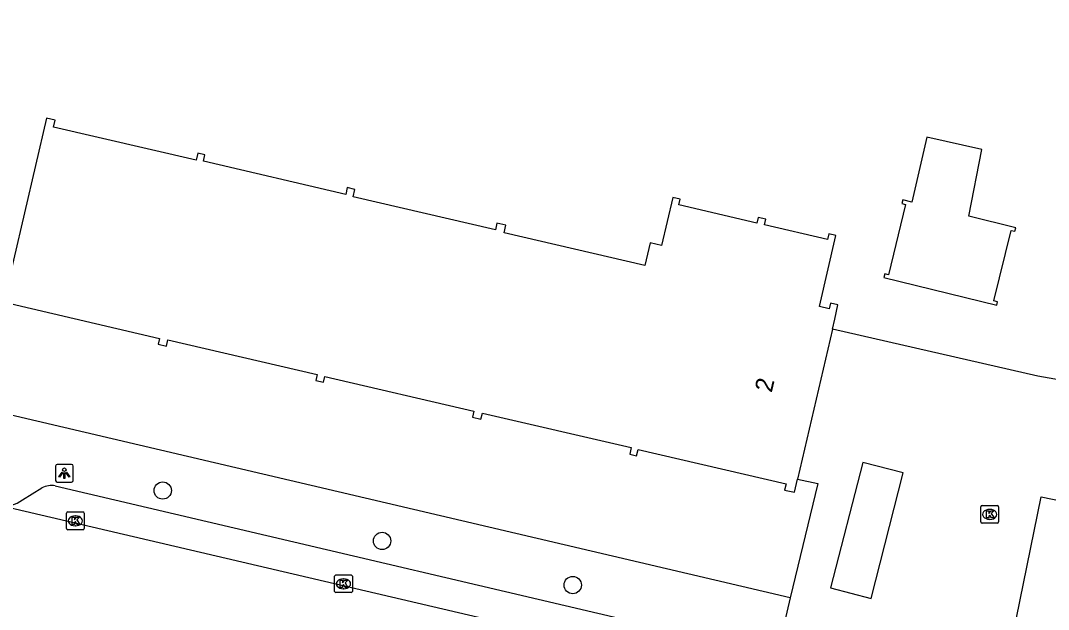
# Model space of a CAD drawing. Extents: x 163686 to 164493, y 382719 to 383870.
# Drawn here: x 163913.6 to 163971.7, y 383334.7 to 383368 of the extents above; entities that cross this region are included whole.
import ezdxf

# ---------------------------------------------------------------- set-up
doc = ezdxf.new("R2010")
doc.units = 0
for name, color, linetype in [('IMGEO_Boom', 7, 'Continuous'), ('IMGEO_Kolk', 7, 'Continuous'), ('IMGEO_Lichtpunt', 7, 'Continuous'), ('IMGEO_Pand', 7, 'Continuous'), ('IMGEO_Pand_nummerreeks', 7, 'Continuous'), ('IMGEO_Rijbaan_lokaal_open', 7, 'Continuous'), ('IMGEO_Voetpad_open', 7, 'Continuous')]:
    doc.layers.add(name, color=color, linetype=linetype)

msp = doc.modelspace()

# ---------------------------------------------------------------- linework, layer by layer
at = {"layer": 'IMGEO_Boom'}
for centre in [(163921.64, 383341.41), (163934.047, 383338.559), (163944.827, 383336.066)]:
    msp.add_circle(centre, 0.489, dxfattribs=at)
at = {"layer": 'IMGEO_Kolk'}
for p, q in [((163916.274, 383340.196), (163917.126, 383340.196)), ((163967.905, 383339.635), (163967.905, 383340.487)), ((163967.98, 383340.561), (163968.832, 383340.561)), ((163968.393, 383340.341), (163968.418, 383340.341)), ((163968.906, 383340.487), (163968.906, 383339.635)), ((163916.199, 383339.27), (163916.199, 383340.122)), ((163916.687, 383339.976), (163916.712, 383339.976)), ((163917.2, 383340.122), (163917.2, 383339.27)), ((163968.416, 383339.781), (163968.391, 383339.781)), ((163917.126, 383339.196), (163916.274, 383339.196)), ((163916.71, 383339.416), (163916.685, 383339.416)), ((163968.832, 383339.561), (163967.98, 383339.561)), ((163931.362, 383335.711), (163931.362, 383336.563)), ((163931.437, 383336.637), (163932.289, 383336.637)), ((163931.85, 383336.417), (163931.875, 383336.417)), ((163932.363, 383336.563), (163932.363, 383335.711)), ((163932.289, 383335.637), (163931.437, 383335.637)), ((163931.873, 383335.857), (163931.848, 383335.857))]:
    msp.add_line(p, q, dxfattribs=at)
for points in [[(163916.274, 383340.196), (163917.126, 383340.196)], [(163967.905, 383339.635), (163967.905, 383340.487)], [(163967.98, 383340.561), (163968.832, 383340.561)], [(163968.226, 383340.261), (163968.349, 383340.261), (163968.349, 383340.11), (163968.479, 383340.261), (163968.643, 383340.261), (163968.497, 383340.11), (163968.65, 383339.861), (163968.498, 383339.861), (163968.413, 383340.025), (163968.349, 383339.958), (163968.349, 383339.861), (163968.226, 383339.861), (163968.226, 383340.261)], [(163968.906, 383340.487), (163968.906, 383339.635)], [(163916.199, 383339.27), (163916.199, 383340.122)], [(163916.52, 383339.896), (163916.643, 383339.896), (163916.643, 383339.745), (163916.773, 383339.896), (163916.937, 383339.896), (163916.791, 383339.745), (163916.944, 383339.496), (163916.792, 383339.496), (163916.707, 383339.66), (163916.643, 383339.593), (163916.643, 383339.496), (163916.52, 383339.496), (163916.52, 383339.896)], [(163917.2, 383340.122), (163917.2, 383339.27)], [(163917.126, 383339.196), (163916.274, 383339.196)], [(163968.832, 383339.561), (163967.98, 383339.561)], [(163931.362, 383335.711), (163931.362, 383336.563)], [(163931.437, 383336.637), (163932.289, 383336.637)], [(163931.683, 383336.337), (163931.806, 383336.337), (163931.806, 383336.186), (163931.936, 383336.337), (163932.1, 383336.337), (163931.954, 383336.186), (163932.107, 383335.937), (163931.955, 383335.937), (163931.87, 383336.101), (163931.806, 383336.034), (163931.806, 383335.937), (163931.683, 383335.937), (163931.683, 383336.337)], [(163932.363, 383336.563), (163932.363, 383335.711)], [(163932.289, 383335.637), (163931.437, 383335.637)]]:
    msp.add_lwpolyline(points, dxfattribs=at)
for centre, start, end in [((163916.276, 383340.12), 91.55205, 178.44795), ((163916.276, 383340.12), 91.55205, 178.44795), ((163917.124, 383340.12), 1.55205, 88.44795), ((163917.124, 383340.12), 1.55205, 88.44795), ((163967.982, 383340.485), 91.55205, 178.44795), ((163967.982, 383340.485), 91.55205, 178.44795), ((163968.83, 383340.485), 1.55205, 88.44795), ((163968.83, 383340.485), 1.55205, 88.44795), ((163967.982, 383339.637), 181.55205, 268.44795), ((163967.982, 383339.637), 181.55205, 268.44795), ((163968.83, 383339.637), 271.55205, 358.44795), ((163968.83, 383339.637), 271.55205, 358.44795), ((163916.276, 383339.272), 181.55205, 268.44795), ((163916.276, 383339.272), 181.55205, 268.44795), ((163917.124, 383339.272), 271.55205, 358.44795), ((163917.124, 383339.272), 271.55205, 358.44795), ((163931.439, 383336.561), 91.55205, 178.44795), ((163931.439, 383336.561), 91.55205, 178.44795), ((163932.287, 383336.561), 1.55205, 88.44795), ((163932.287, 383336.561), 1.55205, 88.44795), ((163931.439, 383335.713), 181.55205, 268.44795), ((163931.439, 383335.713), 181.55205, 268.44795), ((163932.287, 383335.713), 271.55205, 358.44795), ((163932.287, 383335.713), 271.55205, 358.44795)]:
    msp.add_arc(centre, 0.0765, start, end, dxfattribs=at)
for centre, major_axis, ratio, start_param, end_param in [((163968.392, 383340.061), (-0.387, 0.002), 0.722429, 4.712389, 7.853982), ((163968.417, 383340.061), (-0.39, 0.002), 0.717154, 1.570796, 4.712389), ((163916.686, 383339.696), (-0.387, 0.002), 0.722429, 4.712389, 7.853982), ((163916.711, 383339.696), (-0.39, 0.002), 0.717154, 1.570796, 4.712389), ((163931.849, 383336.137), (-0.387, 0.002), 0.722429, 4.712389, 7.853982), ((163931.874, 383336.137), (-0.39, 0.002), 0.717154, 1.570796, 4.712389)]:
    msp.add_ellipse(centre, major_axis=major_axis, ratio=ratio, start_param=start_param, end_param=end_param, dxfattribs=at)
at = {"layer": 'IMGEO_Lichtpunt'}
for p, q in [((163915.58, 383342.789), (163915.58, 383341.982)), ((163915.58, 383342.789), (163915.58, 383341.982)), ((163916.482, 383342.884), (163915.674, 383342.884)), ((163916.482, 383342.884), (163915.674, 383342.884)), ((163916.576, 383341.982), (163916.576, 383342.789)), ((163916.576, 383341.982), (163916.576, 383342.789)), ((163915.674, 383341.888), (163916.482, 383341.888)), ((163915.674, 383341.888), (163916.482, 383341.888))]:
    msp.add_line(p, q, dxfattribs=at)
for points in [[(163915.954, 383342.453), (163915.993, 383342.425), (163915.805, 383342.163), (163915.767, 383342.19), (163915.954, 383342.453)], [(163916.056, 383342.405), (163916.103, 383342.405), (163916.103, 383342.083), (163916.056, 383342.083), (163916.056, 383342.405)], [(163916.166, 383342.425), (163916.204, 383342.452), (163916.391, 383342.19), (163916.352, 383342.162), (163916.166, 383342.425)]]:
    msp.add_lwpolyline(points, dxfattribs=at)
msp.add_circle((163916.079, 383342.587), 0.0994, dxfattribs=at)
for centre, start, end in [((163915.674, 383342.789), 90, 180), ((163915.674, 383342.789), 90, 180), ((163916.482, 383342.789), 0, 90), ((163916.482, 383342.789), 0, 90), ((163915.674, 383341.982), 180, 270), ((163915.674, 383341.982), 180, 270), ((163916.482, 383341.982), 270, 0), ((163916.482, 383341.982), 270, 360)]:
    msp.add_arc(centre, 0.0946, start, end, dxfattribs=at)
at = {"layer": 'IMGEO_Pand'}
for points in [[(163959.506, 383350.535), (163959.638, 383351.103), (163959.826, 383351.91), (163959.408, 383352.008), (163959.334, 383351.687), (163958.779, 383351.816), (163959.71, 383355.82), (163959.301, 383355.916), (163959.227, 383355.595), (163955.662, 383356.424), (163955.737, 383356.746), (163955.319, 383356.844), (163955.245, 383356.523), (163950.823, 383357.551), (163950.898, 383357.873), (163950.48, 383357.971), (163949.849, 383355.254), (163949.207, 383355.404), (163948.911, 383354.128), (163940.94, 383355.98), (163941.039, 383356.405), (163940.538, 383356.521), (163940.45, 383356.139), (163932.415, 383358.006), (163932.513, 383358.431), (163932.079, 383358.532), (163931.991, 383358.152), (163923.945, 383360.021), (163924.03, 383360.386), (163923.632, 383360.479), (163923.539, 383360.079), (163915.46, 383361.956), (163915.551, 383362.347), (163915.07, 383362.459), (163912.585, 383351.763)], [(163968.799, 383351.882), (163968.85, 383352.084), (163968.638, 383352.137), (163969.612, 383356.117), (163969.825, 383356.066), (163969.875, 383356.268), (163967.233, 383356.915), (163967.952, 383360.688), (163964.856, 383361.381), (163964.01, 383357.707), (163963.495, 383357.833), (163963.445, 383357.63), (163963.646, 383357.58), (163962.682, 383353.6), (163962.469, 383353.651), (163962.419, 383353.448), (163968.799, 383351.882)], [(163913.015, 383351.973), (163921.455, 383350.012), (163921.378, 383349.684), (163921.857, 383349.573), (163921.938, 383349.921), (163930.37, 383347.962), (163930.294, 383347.635), (163930.727, 383347.534), (163930.803, 383347.859), (163939.23, 383345.901), (163939.15, 383345.555), (163939.637, 383345.442), (163939.718, 383345.792), (163948.137, 383343.836), (163948.052, 383343.47), (163948.439, 383343.38), (163948.519, 383343.725), (163956.888, 383341.78), (163956.809, 383341.437), (163957.362, 383341.308), (163957.536, 383342.058)], [(163959.506, 383350.535), (163957.536, 383342.058)]]:
    msp.add_lwpolyline(points, dxfattribs=at)
at = {"layer": 'IMGEO_Rijbaan_lokaal_open'}
msp.add_lwpolyline([(163969.564, 383327.202), (163912.387, 383340.568)], dxfattribs=at)
at = {"layer": 'IMGEO_Voetpad_open'}
for points in [[(164018.273, 383380.708), (164008.149, 383341.36), (163971.121, 383347.881), (163959.506, 383350.535)], [(163957.118, 383335.345), (163905.989, 383347.327)], [(163961.238, 383342.998), (163959.396, 383335.908), (163961.695, 383335.309), (163963.519, 383342.401), (163961.238, 383342.998)], [(163957.536, 383342.058), (163958.691, 383341.807), (163957.118, 383335.345)], [(163913.714, 383340.882), (163914.804, 383341.555)], [(163915.561, 383341.678), (163956.365, 383332.095)], [(163976.309, 383332.898), (163969.912, 383334.215), (163971.319, 383341.052), (163977.717, 383339.735), (163976.309, 383332.898)], [(163957.118, 383335.345), (163956.365, 383332.095)]]:
    msp.add_lwpolyline(points, dxfattribs=at)
for centre, radius, start, end in [((163915.377, 383340.421), 1.27, 81.65727, 116.80066), ((163912.698, 383342.215), 1.676, 259.31283, 307.31256)]:
    msp.add_arc(centre, radius, start, end, dxfattribs=at)

# ---------------------------------------------------------------- texts
at = {"layer": 'IMGEO_Pand_nummerreeks'}
msp.add_text('2', height=1, rotation=76.91621, dxfattribs=at).set_placement((163956.076, 383346.909))

doc.saveas('drawing.dxf')
